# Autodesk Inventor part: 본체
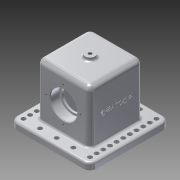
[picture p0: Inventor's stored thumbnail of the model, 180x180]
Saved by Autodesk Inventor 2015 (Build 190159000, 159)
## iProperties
Created: 2018-11
Part Number: 본체
Material: 알루미늄 6061
Document SubType Name: Modeling
Designer: now
Density: 2.7 g/cm^3
Appearance: 알루미늄 - 평지
Mass: 1016.94 g
Surface Area: 777.733 cm^2
Volume: 376.643 cm^3
Author: now
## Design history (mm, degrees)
sketch "스케치1"
  geometry: L1 (-60, -60)-(60, -60); L2 (60, -60)-(60, 60); L3 (60, 60)-(-60, 60); L4 (-60, 60)-(-60, -60); L5 (-60, -60)-(60, 60); L6 (60, -60)-(-60, 60); 1 further point
  constraints: 12 end point, 2 midpoint, 2 parallel, 1 horizontal, 1 perpendicular
  dimensions: "d0" = 120 distance of L3.end L1.start; "d1" = 120 distance of L2.end L3.end
extrude "돌출1" new body sketch "스케치1" distance "d2" = 10; taper "d3" = 0 deg
sketch "스케치2"
  geometry: L1 (-40, -40)-(40, -40); L2 (40, -40)-(40, 40); L3 (40, 40)-(-40, 40); L4 (-40, 40)-(-40, -40); L5 (-40, -40)-(40, 40); L6 (40, -40)-(-40, 40); 1 further point
  constraints: 12 end point, 2 midpoint, 2 parallel, 1 horizontal, 1 perpendicular
  dimensions: "d4" = 80 distance of L3.end L1.start; "d5" = 80 distance of L2.end L3.end
extrude "돌출2" join sketch "스케치2" distance "d6" = 80; taper "d7" = 0 deg
node "작업 평면1"
sketch "스케치3"
  geometry: C1 r 7.5 at (0, 0); 1 further point
  constraints: 1 centre point, 1 coincident
  dimensions: "d9" = 15 diameter of C1
extrude "돌출3" join sketch "스케치3" stored distance "d10" = 80; taper "d11" = 0 deg
sketch "스케치4"
  geometry: C1 r 7.5 at (0, 0) reference
hole "구멍1" sketch "스케치4" at (0, 0) diameter "d12" = 4.917; stored, may be unused: countersink angle "d16" = 90 deg, drill point angle "d18" = 118 deg; dims "d13" = 12, "d14" = 4, "d15" = 2, "d17" = 45
sketch "스케치5"
  geometry: L1 (30, -23)-(-30, -23); L2 (-30, -23)-(-30, 23); L3 (-30, 23)-(30, 23); L4 (30, 23)-(30, -23); L5 (30, -23)-(-30, 23); L6 (-30, -23)-(30, 23); 1 further point
  constraints: 12 end point, 2 midpoint, 2 parallel, 1 horizontal, 1 perpendicular
  dimensions: "d19" = 60 distance of L1.start L1.end; "d20" = 46 distance of L1.end L2.end
extrude "돌출4" cut sketch "스케치5" distance "d21" = 80; taper "d22" = 0 deg
fillet "모깎기1" dims "d23" = 3
fillet "모깎기2" dims "d24" = 3
sketch "스케치6"
  geometry: L1 (-20, -10)-(100, -10) reference; C1 r 16.5 at (40, 38); 1 further point
  constraints: 1 centre point
  dimensions: "d25" = 33 diameter of C1; "d26" = 48 distance from line of L1 C1.centre
extrude "돌출5" cut sketch "스케치6" stored distance "d27" = 80; taper "d28" = 0 deg
sketch "스케치7"
  geometry: C1 r 16.5 at (40, 38) reference; C2 r 20 at (40, 38); 1 further point
  constraints: 1 centre point, 1 coincident
  dimensions: "d29" = 40 diameter of C2
extrude "돌출6" cut sketch "스케치7" distance "d30" = 14; taper "d31" = 0 deg
chamfer "모따기1" distance "d32" = 1; stored, may be unused: second distance "d33" = 2, angle "d34" = 45 deg
chamfer "모따기2" distance "d35" = 1; stored, may be unused: second distance "d36" = 2, angle "d37" = 45 deg
sketch "스케치8"
  geometry: C1 r 21 at (40, 38) reference; C2 r 20 at (40, 38) reference; 2 further points
  constraints: 1 vertical alignment
  dimensions: "d38" = 26 distance of point (40, 64) C2.centre
hole "구멍2" sketch "스케치8" at (40, 64) diameter "d39" = 3.242; stored, may be unused: countersink angle "d43" = 90 deg, drill point angle "d45" = 118 deg; dims "d40" = 8, "d41" = 4, "d42" = 2, "d44" = 10
fillet "모깎기3" dims "d49" = 10
fillet "모깎기4" dims "d50" = 3
sketch "스케치9"
  geometry: C1 r 3.3 at (-50, -50); A1 r 7 centre (-50, -50) between (-57, -50) and (-50, -57) reference; 1 further point
  constraints: 1 centre point, 1 coincident
  dimensions: "d51" = 6.6 diameter of C1
extrude "돌출7" cut sketch "스케치9" stored distance "d52" = 10; taper "d53" = 0 deg
fillet "모깎기5" dims "d72" = 8
fillet "모깎기6" dims "d73" = 8
fillet "모깎기7" dims "d74" = 3
sketch "스케치11"
  geometry: L1 (82, -18)-(82, 82) reference; 3 further points
  constraints: 1 horizontal alignment, 1 midpoint, 1 other
  dimensions: "d75" = 48 distance from line of L1 point (34, 32)
feature "엠보싱1" sketch "스케치11" dims "d0" = 120, "d1" = 120, "d76" = 0.5, "d77" = 0
fillet "모깎기8" dims "d78" = 0.6
node "솔리드1"
mirror "대칭1"
pattern_circular "원형 패턴1" dims angle "d47" = 360 deg
mirror "대칭2"
pattern_linear "직사각형 패턴2" dims "d62" = 10
pattern_linear "직사각형 패턴3" dims "d68" = 25
other parameters: "d8" = 95
